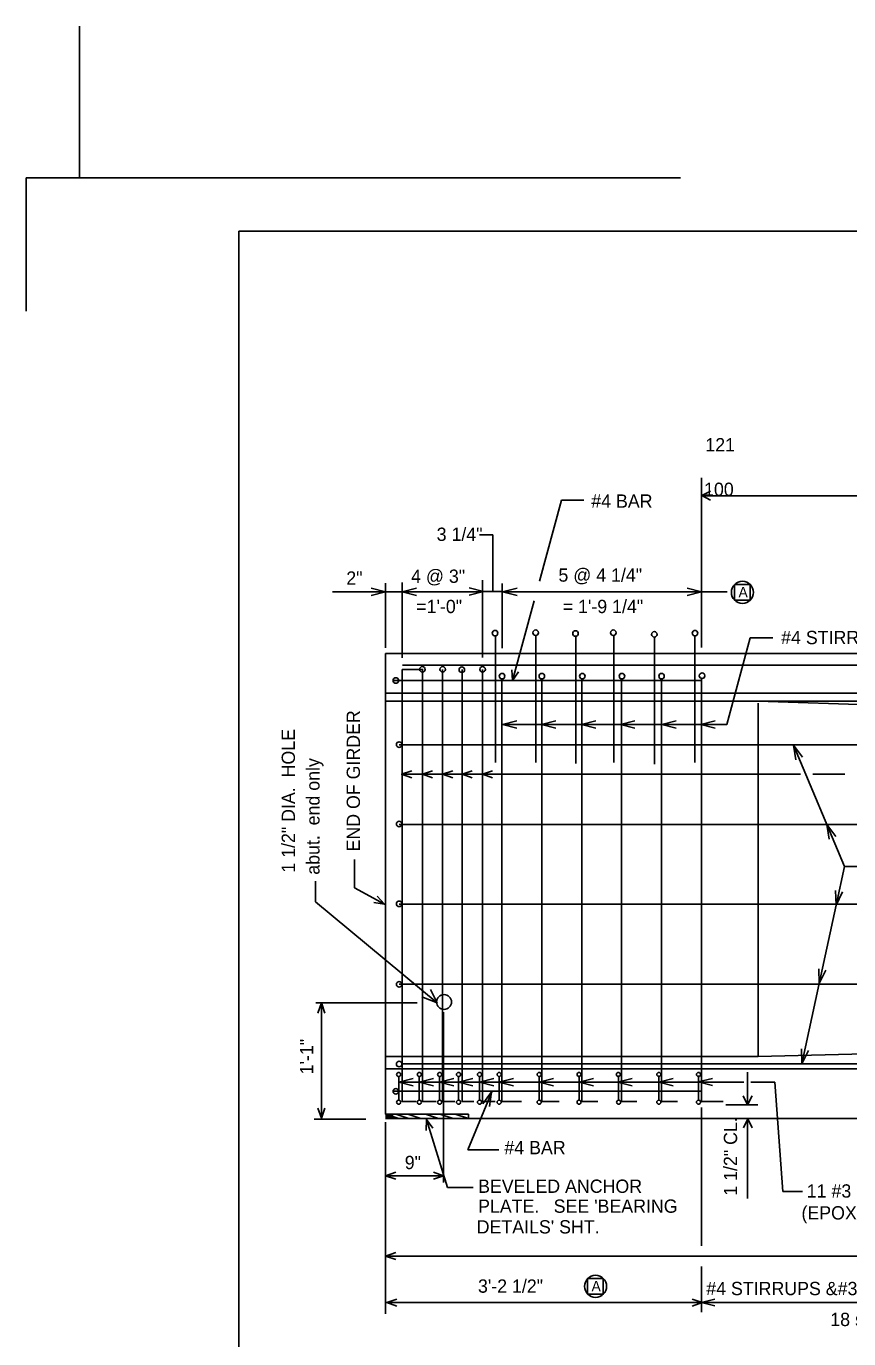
# Model space of a CAD drawing. Extents: x 1005 to 1133, y 2006 to 2074.
# Drawn here: x 1008.43 to 1029.05, y 2040.78 to 2073.7 of the extents above; entities that cross this region are included whole.
import ezdxf

# ---------------------------------------------------------------- set-up
doc = ezdxf.new("R2010")
doc.units = 0
for name, color, linetype in [('Level 1', 7, 'Continuous'), ('Level 2', 7, 'Continuous'), ('Level 5', 7, 'Continuous'), ('Level 6', 7, 'Continuous'), ('Level 60', 7, 'Continuous')]:
    doc.layers.add(name, color=color, linetype=linetype)

msp = doc.modelspace()

# ---------------------------------------------------------------- linework, layer by layer
at = {"layer": 'Level 1'}
for p, q in [((1024.831, 2069.894), (1008.43, 2069.894)), ((1008.43, 2069.894), (1008.43, 2066.554)), ((1013.763, 2012.562), (1013.763, 2068.561)), ((1097.431, 2068.561), (1013.763, 2068.561))]:
    msp.add_line(p, q, dxfattribs=at)
at = {"layer": 'Level 2'}
for p, q in [((1009.763, 2069.894), (1009.763, 2073.698)), ((1025.357, 2058.113), (1025.357, 2062.376)), ((1021.298, 2059.783), (1021.846, 2061.808)), ((1021.846, 2061.808), (1022.41, 2061.808)), ((1025.357, 2061.923), (1054.324, 2061.923)), ((1020.13, 2060.939), (1019.792, 2060.939)), ((1020.13, 2059.522), (1020.13, 2060.939)), ((1019.87, 2057.862), (1019.87, 2059.809)), ((1017.857, 2059.514), (1016.107, 2059.514)), ((1017.441, 2059.514), (1016.171, 2059.514)), ((1017.441, 2059.514), (1017.081, 2059.604)), ((1017.441, 2059.514), (1017.081, 2059.424)), ((1017.441, 2058.106), (1017.441, 2059.732)), ((1017.857, 2057.854), (1017.857, 2059.744)), ((1017.857, 2059.514), (1018.217, 2059.604)), ((1019.87, 2059.514), (1017.857, 2059.514)), ((1017.857, 2059.514), (1018.217, 2059.424)), ((1019.898, 2059.522), (1019.538, 2059.612)), ((1019.898, 2059.522), (1019.538, 2059.432)), ((1020.36, 2059.522), (1019.87, 2059.522)), ((1020.36, 2058.103), (1020.36, 2059.725)), ((1020.36, 2059.514), (1026.005, 2059.514)), ((1020.375, 2059.514), (1020.735, 2059.604)), ((1020.375, 2059.514), (1020.735, 2059.424)), ((1025.357, 2059.514), (1024.997, 2059.604)), ((1025.357, 2059.514), (1024.997, 2059.424)), ((1020.621, 2057.286), (1021.163, 2059.286)), ((1026.195, 2059.303), (1026.195, 2059.303)), ((1020.194, 2058.425), (1020.194, 2055.229)), ((1021.21, 2058.425), (1021.21, 2055.229)), ((1022.207, 2058.404), (1022.207, 2055.208)), ((1023.161, 2058.425), (1023.161, 2055.229)), ((1024.178, 2058.383), (1024.178, 2055.187)), ((1025.195, 2058.425), (1025.195, 2055.229)), ((1025.994, 2056.185), (1026.584, 2058.362)), ((1026.584, 2058.362), (1027.147, 2058.362)), ((1017.441, 2046.413), (1017.441, 2057.969)), ((1017.441, 2057.969), (1038.737, 2057.969)), ((1017.857, 2057.562), (1018.382, 2057.562)), ((1017.857, 2047.379), (1017.857, 2057.562)), ((1017.863, 2057.676), (1031.429, 2057.676)), ((1018.362, 2046.728), (1018.362, 2057.562)), ((1018.87, 2046.728), (1018.87, 2057.562)), ((1019.357, 2046.728), (1019.357, 2057.562)), ((1019.87, 2046.728), (1019.87, 2057.562)), ((1017.64, 2057.286), (1025.357, 2057.286)), ((1020.357, 2046.728), (1020.357, 2057.335)), ((1021.357, 2046.728), (1021.357, 2057.335)), ((1022.357, 2046.728), (1022.357, 2057.325)), ((1023.357, 2046.728), (1023.357, 2057.335)), ((1024.357, 2046.728), (1024.357, 2057.325)), ((1025.357, 2046.728), (1025.357, 2057.335)), ((1038.745, 2056.969), (1017.439, 2056.969)), ((1038.737, 2056.772), (1017.426, 2056.772)), ((1038.441, 2056.386), (1026.782, 2056.772)), ((1026.782, 2047.859), (1026.782, 2056.719)), ((1020.374, 2056.185), (1020.734, 2056.275)), ((1022.351, 2056.185), (1020.374, 2056.185)), ((1020.374, 2056.185), (1020.734, 2056.095)), ((1021.349, 2056.185), (1021.709, 2056.275)), ((1021.349, 2056.185), (1021.709, 2056.095)), ((1022.351, 2056.185), (1022.711, 2056.275)), ((1023.284, 2056.185), (1022.351, 2056.185)), ((1022.351, 2056.185), (1022.711, 2056.095)), ((1023.333, 2056.185), (1023.284, 2056.185)), ((1023.333, 2056.185), (1023.693, 2056.275)), ((1024.362, 2056.185), (1023.333, 2056.185)), ((1023.333, 2056.185), (1023.693, 2056.095)), ((1024.362, 2056.185), (1024.722, 2056.275)), ((1025.347, 2056.185), (1024.362, 2056.185)), ((1024.362, 2056.185), (1024.722, 2056.095)), ((1025.347, 2056.185), (1025.707, 2056.275)), ((1025.347, 2056.185), (1025.994, 2056.185)), ((1025.347, 2056.185), (1025.707, 2056.095)), ((1017.78, 2055.676), (1031.429, 2055.676)), ((1028.945, 2052.627), (1027.669, 2055.663)), ((1027.669, 2055.663), (1027.892, 2055.366)), ((1027.669, 2055.663), (1027.726, 2055.296)), ((1017.842, 2054.936), (1027.842, 2054.936)), ((1028.958, 2054.936), (1028.149, 2054.936)), ((1017.78, 2053.676), (1031.429, 2053.676)), ((1028.504, 2053.676), (1028.726, 2053.379)), ((1028.504, 2053.676), (1028.561, 2053.31)), ((1016.66, 2052.086), (1016.66, 2052.795)), ((1028.945, 2052.627), (1028.735, 2051.653)), ((1029.834, 2052.627), (1028.945, 2052.627)), ((1016.66, 2052.086), (1017.41, 2051.679)), ((1028.735, 2051.653), (1028.723, 2052.024)), ((1028.735, 2051.653), (1028.899, 2051.986)), ((1017.78, 2051.676), (1031.429, 2051.676)), ((1028.735, 2051.653), (1028.311, 2049.688)), ((1028.311, 2049.688), (1028.299, 2050.059)), ((1028.311, 2049.688), (1028.475, 2050.021)), ((1017.78, 2049.676), (1023.804, 2049.676)), ((1023.804, 2049.676), (1031.429, 2049.676)), ((1028.311, 2049.688), (1027.876, 2047.676)), ((1026.782, 2047.859), (1031.222, 2047.964)), ((1027.876, 2047.676), (1027.864, 2048.047)), ((1027.876, 2047.676), (1028.04, 2048.009)), ((1026.782, 2047.859), (1017.441, 2047.859)), ((1017.85, 2047.676), (1031.149, 2047.676)), ((1017.44, 2047.552), (1031.118, 2047.552)), ((1017.769, 2046.782), (1017.769, 2047.355)), ((1017.769, 2047.216), (1018.129, 2047.306)), ((1017.857, 2046.728), (1017.857, 2047.379)), ((1018.28, 2047.216), (1018.64, 2047.306)), ((1018.284, 2046.782), (1018.284, 2047.355)), ((1018.789, 2047.216), (1019.149, 2047.306)), ((1018.793, 2046.782), (1018.793, 2047.355)), ((1019.265, 2047.216), (1019.625, 2047.306)), ((1019.271, 2046.782), (1019.271, 2047.355)), ((1019.79, 2047.215), (1020.15, 2047.305)), ((1019.793, 2046.782), (1019.793, 2047.355)), ((1020.283, 2047.216), (1020.643, 2047.306)), ((1020.286, 2046.782), (1020.286, 2047.355)), ((1021.289, 2046.782), (1021.289, 2047.355)), ((1021.29, 2047.216), (1021.65, 2047.306)), ((1022.289, 2046.782), (1022.289, 2047.379)), ((1022.289, 2047.216), (1022.649, 2047.306)), ((1023.258, 2047.216), (1023.618, 2047.306)), ((1023.278, 2046.782), (1023.278, 2047.379)), ((1024.289, 2046.782), (1024.289, 2047.379)), ((1024.289, 2047.216), (1024.649, 2047.306)), ((1025.274, 2047.22), (1025.634, 2047.31)), ((1025.284, 2046.782), (1025.284, 2047.379)), ((1026.512, 2047.469), (1026.512, 2046.649)), ((1017.64, 2046.986), (1025.357, 2046.986)), ((1017.769, 2047.216), (1018.53, 2047.216)), ((1017.769, 2047.216), (1018.129, 2047.126)), ((1018.28, 2047.216), (1018.64, 2047.126)), ((1018.53, 2047.216), (1019.251, 2047.216)), ((1018.789, 2047.216), (1019.149, 2047.126)), ((1019.251, 2047.216), (1020.274, 2047.216)), ((1019.265, 2047.216), (1019.625, 2047.126)), ((1019.499, 2045.521), (1020.103, 2046.973)), ((1019.79, 2047.215), (1020.15, 2047.125)), ((1020.099, 2046.971), (1019.877, 2046.673)), ((1020.099, 2046.971), (1020.043, 2046.604)), ((1020.274, 2047.216), (1021.29, 2047.216)), ((1020.283, 2047.216), (1020.643, 2047.126)), ((1021.29, 2047.216), (1023.258, 2047.216)), ((1021.29, 2047.216), (1021.65, 2047.126)), ((1022.289, 2047.216), (1022.649, 2047.126)), ((1023.258, 2047.216), (1025.358, 2047.216)), ((1023.258, 2047.216), (1023.618, 2047.126)), ((1024.289, 2047.216), (1024.649, 2047.126)), ((1025.274, 2047.22), (1025.634, 2047.13)), ((1025.358, 2047.216), (1026.419, 2047.216)), ((1026.595, 2047.216), (1027.202, 2047.216)), ((1027.399, 2044.471), (1027.202, 2047.216)), ((1017.857, 2046.728), (1017.857, 2046.765)), ((1017.857, 2046.728), (1018.202, 2046.728)), ((1018.362, 2046.728), (1018.706, 2046.728)), ((1018.87, 2046.728), (1019.174, 2046.728)), ((1019.357, 2046.728), (1019.648, 2046.728)), ((1019.87, 2046.728), (1020.186, 2046.728)), ((1020.357, 2046.728), (1020.851, 2046.728)), ((1021.357, 2046.728), (1021.793, 2046.728)), ((1022.359, 2046.728), (1022.762, 2046.728)), ((1023.357, 2046.728), (1023.743, 2046.728)), ((1024.364, 2046.728), (1024.762, 2046.728)), ((1025.357, 2046.728), (1025.906, 2046.728)), ((1025.97, 2046.649), (1026.774, 2046.649)), ((1017.441, 2046.413), (1017.769, 2046.301)), ((1017.769, 2046.302), (1030.816, 2046.302)), ((1025.357, 2046.576), (1025.357, 2043.109)), ((1026.512, 2046.302), (1026.512, 2044.294)), ((1026.834, 2046.302), (1026.901, 2046.302)), ((1017.441, 2046.208), (1017.441, 2041.404)), ((1020.283, 2045.521), (1019.499, 2045.521)), ((1027.399, 2044.471), (1027.892, 2044.471)), ((1017.441, 2042.85), (1061.731, 2042.85)), ((1025.357, 2042.592), (1025.357, 2041.445)), ((1017.463, 2041.684), (1025.357, 2041.684)), ((1022.511, 2041.897), (1022.511, 2041.897)), ((1025.357, 2041.684), (1037.408, 2041.684))]:
    msp.add_line(p, q, dxfattribs=at)
for points in [[(1025.59, 2061.815), (1025.368, 2061.926), (1025.59, 2062.037)], [(1020.772, 2057.507), (1020.621, 2057.286), (1020.603, 2057.553)], [(1018.095, 2054.848), (1017.842, 2054.936), (1018.095, 2055.024)], [(1018.614, 2054.848), (1018.361, 2054.936), (1018.614, 2055.024)], [(1019.123, 2054.848), (1018.87, 2054.936), (1019.123, 2055.024)], [(1019.611, 2054.848), (1019.357, 2054.936), (1019.611, 2055.024)], [(1020.123, 2054.848), (1019.87, 2054.936), (1020.123, 2055.024)], [(1017.229, 2051.877), (1017.41, 2051.679), (1017.145, 2051.723)], [(1026.628, 2046.869), (1026.517, 2046.647), (1026.406, 2046.869)], [(1026.634, 2046.071), (1026.523, 2046.293), (1026.411, 2046.071)], [(1017.694, 2042.763), (1017.441, 2042.85), (1017.694, 2042.938)], [(1017.724, 2041.597), (1017.471, 2041.684), (1017.724, 2041.772)], [(1025.124, 2041.772), (1025.378, 2041.684), (1025.124, 2041.597)], [(1025.691, 2041.601), (1025.357, 2041.684), (1025.691, 2041.768)]]:
    msp.add_lwpolyline(points, dxfattribs=at)
for points in [[(1026.191, 2059.694), (1026.191, 2059.302), (1026.583, 2059.302), (1026.583, 2059.694)], [(1022.506, 2042.288), (1022.506, 2041.895), (1022.898, 2041.895), (1022.898, 2042.288)]]:
    msp.add_lwpolyline(points, close=True, dxfattribs=at)
for centre, radius in [((1026.388, 2059.499), 0.277), ((1020.184, 2058.477), 0.0694), ((1021.203, 2058.487), 0.0694), ((1022.202, 2058.467), 0.0694), ((1023.149, 2058.487), 0.0694), ((1024.178, 2058.446), 0.0694), ((1025.198, 2058.477), 0.0694), ((1018.362, 2057.568), 0.0694), ((1018.871, 2057.568), 0.0694), ((1019.352, 2057.558), 0.0694), ((1019.871, 2057.568), 0.0694), ((1025.375, 2057.408), 0.0694), ((1017.697, 2057.288), 0.0694), ((1020.36, 2057.397), 0.0694), ((1021.358, 2057.397), 0.0694), ((1022.372, 2057.397), 0.0694), ((1023.366, 2057.397), 0.0694), ((1024.359, 2057.397), 0.0694), ((1017.781, 2055.681), 0.0694), ((1017.781, 2053.689), 0.0694), ((1017.781, 2051.688), 0.0694), ((1017.781, 2049.669), 0.0694), ((1017.781, 2047.668), 0.0694), ((1017.767, 2047.407), 0.052), ((1018.287, 2047.407), 0.052), ((1018.796, 2047.407), 0.052), ((1019.269, 2047.407), 0.052), ((1019.796, 2047.407), 0.052), ((1020.287, 2047.407), 0.052), ((1021.291, 2047.407), 0.052), ((1022.291, 2047.407), 0.052), ((1023.274, 2047.407), 0.052), ((1024.291, 2047.407), 0.052), ((1025.286, 2047.407), 0.052), ((1017.697, 2046.984), 0.0694), ((1017.767, 2046.713), 0.052), ((1018.287, 2046.713), 0.052), ((1018.796, 2046.713), 0.052), ((1019.269, 2046.713), 0.052), ((1019.796, 2046.713), 0.052), ((1020.287, 2046.713), 0.052), ((1021.291, 2046.713), 0.052), ((1022.291, 2046.713), 0.052), ((1023.282, 2046.713), 0.052), ((1024.291, 2046.713), 0.052), ((1025.286, 2046.713), 0.052), ((1022.703, 2042.093), 0.277)]:
    msp.add_circle(centre, radius, dxfattribs=at)
at = {"layer": 'Level 5'}
for p, q in [((1015.685, 2051.734), (1015.685, 2052.253)), ((1015.685, 2051.734), (1018.731, 2049.207)), ((1018.731, 2049.207), (1018.349, 2049.352)), ((1018.731, 2049.207), (1018.562, 2049.539)), ((1018.232, 2049.203), (1015.688, 2049.203)), ((1015.829, 2046.311), (1015.829, 2049.201)), ((1018.888, 2048.97), (1018.888, 2044.7)), ((1016.94, 2046.287), (1015.65, 2046.287)), ((1018.888, 2044.867), (1017.441, 2044.867))]:
    msp.add_line(p, q, dxfattribs=at)
for points in [[(1015.741, 2048.948), (1015.829, 2049.201), (1015.916, 2048.948)], [(1015.741, 2048.948), (1015.829, 2049.201), (1015.916, 2048.948)], [(1015.916, 2046.565), (1015.829, 2046.311), (1015.741, 2046.565)], [(1017.694, 2044.779), (1017.441, 2044.867), (1017.694, 2044.955)], [(1018.641, 2044.779), (1018.894, 2044.867), (1018.641, 2044.955)]]:
    msp.add_lwpolyline(points, dxfattribs=at)
msp.add_circle((1018.906, 2049.225), 0.186, dxfattribs=at)
at = {"layer": 'Level 6'}
for p, q in [((1017.609, 2046.413), (1017.441, 2046.413)), ((1017.441, 2046.405), (1017.609, 2046.405)), ((1017.441, 2046.395), (1017.609, 2046.395)), ((1017.441, 2046.385), (1017.609, 2046.385)), ((1017.441, 2046.375), (1017.609, 2046.375)), ((1017.441, 2046.365), (1017.609, 2046.365)), ((1017.441, 2046.355), (1017.609, 2046.355)), ((1017.441, 2046.345), (1017.609, 2046.345)), ((1017.441, 2046.335), (1017.609, 2046.335)), ((1017.441, 2046.325), (1017.609, 2046.325)), ((1017.441, 2046.315), (1017.609, 2046.315)), ((1017.441, 2046.305), (1017.609, 2046.305)), ((1017.609, 2046.302), (1017.441, 2046.302)), ((1017.698, 2046.413), (1018.025, 2046.302)), ((1017.999, 2046.413), (1018.327, 2046.301)), ((1018.44, 2046.41), (1018.768, 2046.299)), ((1018.803, 2046.413), (1019.131, 2046.302)), ((1019.188, 2046.415), (1019.515, 2046.304)), ((1018.466, 2046.274), (1018.99, 2044.573)), ((1019.632, 2044.573), (1018.99, 2044.573))]:
    msp.add_line(p, q, dxfattribs=at)
msp.add_lwpolyline([(1019.518, 2046.413), (1017.609, 2046.413), (1017.609, 2046.302), (1019.518, 2046.302)], close=True, dxfattribs=at)
msp.add_lwpolyline([(1018.457, 2046.006), (1018.466, 2046.274), (1018.625, 2046.058)], dxfattribs=at)

# ---------------------------------------------------------------- texts
at = {"layer": 'Level 2'}
for s, height, p in [('#4 BAR', 0.3333, (1022.597, 2061.623)), ('3 1/4"', 0.3333, (1018.72, 2060.79)), ('5 @ 4 1/4"', 0.3333, (1021.773, 2059.767)), ('2"', 0.3333, (1016.454, 2059.691)), ('4 @ 3"', 0.3333, (1018.079, 2059.738)), ('A', 0.261, (1026.288, 2059.374)), ('=1\'-0"', 0.3333, (1018.209, 2058.979)), ('= 1\'-9 1/4"', 0.33333, (1021.882, 2058.979)), ('#4 STIRRUPS (4 1/2" leg)', 0.33333, (1027.357, 2058.2)), ('#4 BAR', 0.3333, (1020.418, 2045.406)), ('11 #3 BARS', 0.3333, (1028, 2044.319)), ('(EPOXY COATED)', 0.33333, (1027.867, 2043.77)), ('3\'-2 1/2"', 0.3333, (1019.756, 2041.933)), ('A', 0.261, (1022.603, 2041.967)), ('#4 STIRRUPS &#3 BARS @ 5" (EPOXY COATED)', 0.33333, (1025.48, 2041.872)), ('18 spa. at 5"= 7\'-6"', 0.33333, (1028.59, 2041.097))]:
    msp.add_text(s, height=height, dxfattribs=at).set_placement(p)
for s, height, p in [('END OF GIRDER', 0.33333, (1016.797, 2053.001)), ('1 1/2" CL.', 0.3333, (1026.254, 2044.367))]:
    msp.add_text(s, height=height, rotation=90, dxfattribs=at).set_placement(p)
at = {"layer": 'Level 5'}
for s, height, p in [('1 1/2" DIA.  HOLE', 0.33333, (1015.167, 2052.47)), ('abut.  end only', 0.33333, (1015.783, 2052.417)), ('1\'-1"', 0.3333, (1015.626, 2047.411))]:
    msp.add_text(s, height=height, rotation=90, dxfattribs=at).set_placement(p)
msp.add_text('9"', height=0.3333, dxfattribs=at).set_placement((1017.92, 2045.033))
at = {"layer": 'Level 6'}
for s, height, p in [('BEVELED ANCHOR', 0.33333, (1019.759, 2044.438)), ('PLATE.', 0.3333, (1019.759, 2043.938)), ("SEE 'BEARING", 0.33333, (1021.654, 2043.938)), ("DETAILS' SHT.", 0.33333, (1019.724, 2043.419))]:
    msp.add_text(s, height=height, dxfattribs=at).set_placement(p)
at = {"layer": 'Level 60'}
for s, p in [('121', (1025.457, 2063.035)), ('100', (1025.425, 2061.918))]:
    msp.add_text(s, height=0.3333, dxfattribs=at).set_placement(p)

doc.saveas('drawing.dxf')
